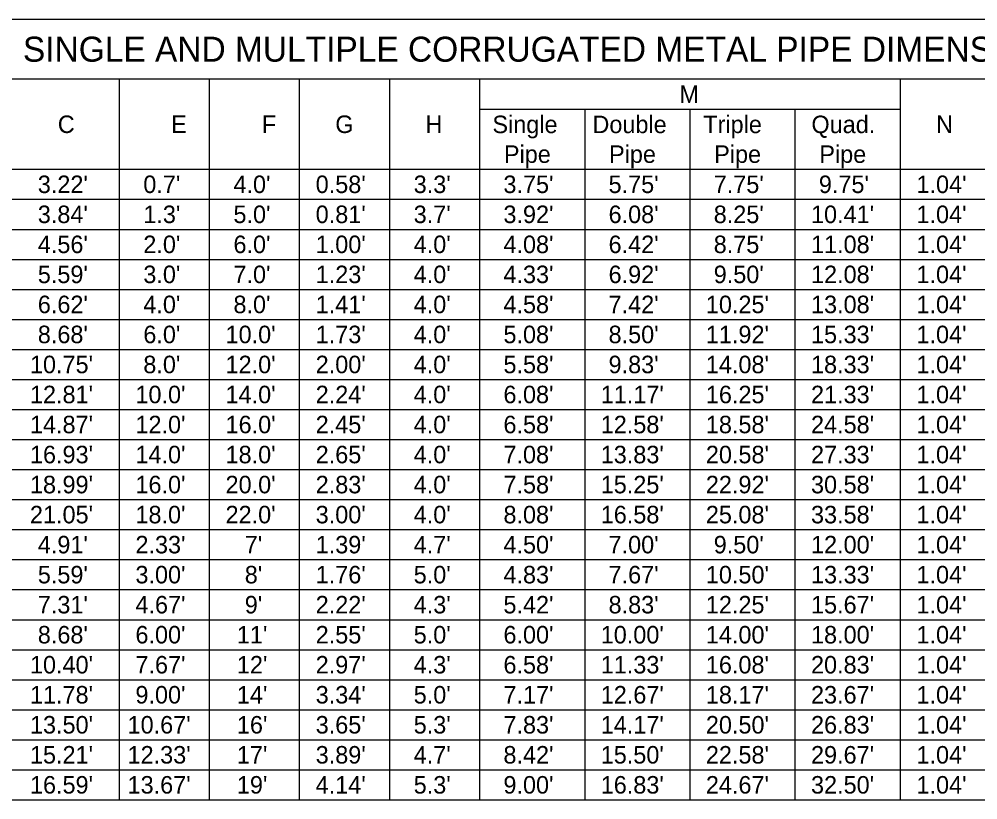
# Model space of a CAD drawing. Extents: x 2 to 14.4, y 0 to 6.5.
# Drawn here: x 4.481 to 8.31, y 3.39 to 6.51 of the extents above; entities that cross this region are included whole.
import ezdxf

# ---------------------------------------------------------------- set-up
doc = ezdxf.new("R2010")
doc.units = 0
doc.layers.add('TextNotes', color=7, linetype='Continuous')
doc.layers.add('TextTables', color=7, linetype='Continuous')

msp = doc.modelspace()

# ---------------------------------------------------------------- linework, layer by layer
at = {"layer": 'TextTables'}
msp.add_line((2, 6.51), (13.4, 6.51), dxfattribs=at)
for points in [[(13.4, 6.27), (11.72, 6.27), (10.04, 6.27), (8.36, 6.27), (8, 6.27), (6.32, 6.27), (5.96, 6.27), (5.6, 6.27), (5.24, 6.27), (4.88, 6.27), (4.46, 6.27), (3.98, 6.27), (3.56, 6.27), (3.14, 6.27), (2.84, 6.27), (2.54, 6.27), (2.24, 6.27), (2, 6.27)], [(4.88, 6.27), (4.88, 5.91), (4.88, 5.79), (4.88, 5.67), (4.88, 5.55), (4.88, 5.43), (4.88, 5.31), (4.88, 5.19), (4.88, 5.07), (4.88, 4.95), (4.88, 4.83), (4.88, 4.71), (4.88, 4.59), (4.88, 4.47), (4.88, 4.35), (4.88, 4.23), (4.88, 4.11), (4.88, 3.99), (4.88, 3.87), (4.88, 3.75), (4.88, 3.63), (4.88, 3.51), (4.88, 3.39)], [(5.24, 6.27), (5.24, 5.91), (5.24, 5.79), (5.24, 5.67), (5.24, 5.55), (5.24, 5.43), (5.24, 5.31), (5.24, 5.19), (5.24, 5.07), (5.24, 4.95), (5.24, 4.83), (5.24, 4.71), (5.24, 4.59), (5.24, 4.47), (5.24, 4.35), (5.24, 4.23), (5.24, 4.11), (5.24, 3.99), (5.24, 3.87), (5.24, 3.75), (5.24, 3.63), (5.24, 3.51), (5.24, 3.39)], [(5.6, 6.27), (5.6, 5.91), (5.6, 5.79), (5.6, 5.67), (5.6, 5.55), (5.6, 5.43), (5.6, 5.31), (5.6, 5.19), (5.6, 5.07), (5.6, 4.95), (5.6, 4.83), (5.6, 4.71), (5.6, 4.59), (5.6, 4.47), (5.6, 4.35), (5.6, 4.23), (5.6, 4.11), (5.6, 3.99), (5.6, 3.87), (5.6, 3.75), (5.6, 3.63), (5.6, 3.51), (5.6, 3.39)], [(5.96, 6.27), (5.96, 5.91), (5.96, 5.79), (5.96, 5.67), (5.96, 5.55), (5.96, 5.43), (5.96, 5.31), (5.96, 5.19), (5.96, 5.07), (5.96, 4.95), (5.96, 4.83), (5.96, 4.71), (5.96, 4.59), (5.96, 4.47), (5.96, 4.35), (5.96, 4.23), (5.96, 4.11), (5.96, 3.99), (5.96, 3.87), (5.96, 3.75), (5.96, 3.63), (5.96, 3.51), (5.96, 3.39)], [(6.32, 6.27), (6.32, 6.15), (6.32, 5.91), (6.32, 5.79), (6.32, 5.67), (6.32, 5.55), (6.32, 5.43), (6.32, 5.31), (6.32, 5.19), (6.32, 5.07), (6.32, 4.95), (6.32, 4.83), (6.32, 4.71), (6.32, 4.59), (6.32, 4.47), (6.32, 4.35), (6.32, 4.23), (6.32, 4.11), (6.32, 3.99), (6.32, 3.87), (6.32, 3.75), (6.32, 3.63), (6.32, 3.51), (6.32, 3.39)], [(8, 6.27), (8, 6.15), (8, 5.91), (8, 5.79), (8, 5.67), (8, 5.55), (8, 5.43), (8, 5.31), (8, 5.19), (8, 5.07), (8, 4.95), (8, 4.83), (8, 4.71), (8, 4.59), (8, 4.47), (8, 4.35), (8, 4.23), (8, 4.11), (8, 3.99), (8, 3.87), (8, 3.75), (8, 3.63), (8, 3.51), (8, 3.39)], [(6.32, 6.15), (6.74, 6.15), (7.16, 6.15), (7.58, 6.15), (8, 6.15)], [(6.74, 6.15), (6.74, 5.91), (6.74, 5.79), (6.74, 5.67), (6.74, 5.55), (6.74, 5.43), (6.74, 5.31), (6.74, 5.19), (6.74, 5.07), (6.74, 4.95), (6.74, 4.83), (6.74, 4.71), (6.74, 4.59), (6.74, 4.47), (6.74, 4.35), (6.74, 4.23), (6.74, 4.11), (6.74, 3.99), (6.74, 3.87), (6.74, 3.75), (6.74, 3.63), (6.74, 3.51), (6.74, 3.39)], [(7.16, 6.15), (7.16, 5.91), (7.16, 5.79), (7.16, 5.67), (7.16, 5.55), (7.16, 5.43), (7.16, 5.31), (7.16, 5.19), (7.16, 5.07), (7.16, 4.95), (7.16, 4.83), (7.16, 4.71), (7.16, 4.59), (7.16, 4.47), (7.16, 4.35), (7.16, 4.23), (7.16, 4.11), (7.16, 3.99), (7.16, 3.87), (7.16, 3.75), (7.16, 3.63), (7.16, 3.51), (7.16, 3.39)], [(7.58, 6.15), (7.58, 5.91), (7.58, 5.79), (7.58, 5.67), (7.58, 5.55), (7.58, 5.43), (7.58, 5.31), (7.58, 5.19), (7.58, 5.07), (7.58, 4.95), (7.58, 4.83), (7.58, 4.71), (7.58, 4.59), (7.58, 4.47), (7.58, 4.35), (7.58, 4.23), (7.58, 4.11), (7.58, 3.99), (7.58, 3.87), (7.58, 3.75), (7.58, 3.63), (7.58, 3.51), (7.58, 3.39)], [(2, 5.91), (2.24, 5.91), (2.54, 5.91), (2.84, 5.91), (3.14, 5.91), (3.56, 5.91), (3.98, 5.91), (4.46, 5.91), (4.88, 5.91), (5.24, 5.91), (5.6, 5.91), (5.96, 5.91), (6.32, 5.91), (6.74, 5.91), (7.16, 5.91), (7.58, 5.91), (8, 5.91), (8.36, 5.91)], [(2.24, 5.79), (2.54, 5.79), (2.84, 5.79), (3.14, 5.79), (3.56, 5.79), (3.98, 5.79), (4.46, 5.79), (4.88, 5.79), (5.24, 5.79), (5.6, 5.79), (5.96, 5.79), (6.32, 5.79), (6.74, 5.79), (7.16, 5.79), (7.58, 5.79), (8, 5.79), (8.36, 5.79)], [(2.24, 5.67), (2.54, 5.67), (2.84, 5.67), (3.14, 5.67), (3.56, 5.67), (3.98, 5.67), (4.46, 5.67), (4.88, 5.67), (5.24, 5.67), (5.6, 5.67), (5.96, 5.67), (6.32, 5.67), (6.74, 5.67), (7.16, 5.67), (7.58, 5.67), (8, 5.67), (8.36, 5.67)], [(2.24, 5.55), (2.54, 5.55), (2.84, 5.55), (3.14, 5.55), (3.56, 5.55), (3.98, 5.55), (4.46, 5.55), (4.88, 5.55), (5.24, 5.55), (5.6, 5.55), (5.96, 5.55), (6.32, 5.55), (6.74, 5.55), (7.16, 5.55), (7.58, 5.55), (8, 5.55), (8.36, 5.55)], [(2.24, 5.43), (2.54, 5.43), (2.84, 5.43), (3.14, 5.43), (3.56, 5.43), (3.98, 5.43), (4.46, 5.43), (4.88, 5.43), (5.24, 5.43), (5.6, 5.43), (5.96, 5.43), (6.32, 5.43), (6.74, 5.43), (7.16, 5.43), (7.58, 5.43), (8, 5.43), (8.36, 5.43)], [(2.24, 5.31), (2.54, 5.31), (2.84, 5.31), (3.14, 5.31), (3.56, 5.31), (3.98, 5.31), (4.46, 5.31), (4.88, 5.31), (5.24, 5.31), (5.6, 5.31), (5.96, 5.31), (6.32, 5.31), (6.74, 5.31), (7.16, 5.31), (7.58, 5.31), (8, 5.31), (8.36, 5.31)], [(2.24, 5.19), (2.54, 5.19), (2.84, 5.19), (3.14, 5.19), (3.56, 5.19), (3.98, 5.19), (4.46, 5.19), (4.88, 5.19), (5.24, 5.19), (5.6, 5.19), (5.96, 5.19), (6.32, 5.19), (6.74, 5.19), (7.16, 5.19), (7.58, 5.19), (8, 5.19), (8.36, 5.19)], [(2.24, 5.07), (2.54, 5.07), (2.84, 5.07), (3.14, 5.07), (3.56, 5.07), (3.98, 5.07), (4.46, 5.07), (4.88, 5.07), (5.24, 5.07), (5.6, 5.07), (5.96, 5.07), (6.32, 5.07), (6.74, 5.07), (7.16, 5.07), (7.58, 5.07), (8, 5.07), (8.36, 5.07)], [(2.24, 4.95), (2.54, 4.95), (2.84, 4.95), (3.14, 4.95), (3.56, 4.95), (3.98, 4.95), (4.46, 4.95), (4.88, 4.95), (5.24, 4.95), (5.6, 4.95), (5.96, 4.95), (6.32, 4.95), (6.74, 4.95), (7.16, 4.95), (7.58, 4.95), (8, 4.95), (8.36, 4.95)], [(2.24, 4.83), (2.54, 4.83), (2.84, 4.83), (3.14, 4.83), (3.56, 4.83), (3.98, 4.83), (4.46, 4.83), (4.88, 4.83), (5.24, 4.83), (5.6, 4.83), (5.96, 4.83), (6.32, 4.83), (6.74, 4.83), (7.16, 4.83), (7.58, 4.83), (8, 4.83), (8.36, 4.83)], [(2.24, 4.71), (2.54, 4.71), (2.84, 4.71), (3.14, 4.71), (3.56, 4.71), (3.98, 4.71), (4.46, 4.71), (4.88, 4.71), (5.24, 4.71), (5.6, 4.71), (5.96, 4.71), (6.32, 4.71), (6.74, 4.71), (7.16, 4.71), (7.58, 4.71), (8, 4.71), (8.36, 4.71)], [(2.24, 4.59), (2.54, 4.59), (2.84, 4.59), (3.14, 4.59), (3.56, 4.59), (3.98, 4.59), (4.46, 4.59), (4.88, 4.59), (5.24, 4.59), (5.6, 4.59), (5.96, 4.59), (6.32, 4.59), (6.74, 4.59), (7.16, 4.59), (7.58, 4.59), (8, 4.59), (8.36, 4.59)], [(2, 4.47), (2.24, 4.47), (2.54, 4.47), (2.84, 4.47), (3.14, 4.47), (3.56, 4.47), (3.98, 4.47), (4.46, 4.47), (4.88, 4.47), (5.24, 4.47), (5.6, 4.47), (5.96, 4.47), (6.32, 4.47), (6.74, 4.47), (7.16, 4.47), (7.58, 4.47), (8, 4.47), (8.36, 4.47)], [(2.24, 4.47), (2.54, 4.47), (2.84, 4.47), (3.14, 4.47), (3.56, 4.47), (3.98, 4.47), (4.46, 4.47), (4.88, 4.47), (5.24, 4.47), (5.6, 4.47), (5.96, 4.47), (6.32, 4.47), (6.74, 4.47), (7.16, 4.47), (7.58, 4.47), (8, 4.47), (8.36, 4.47)], [(2.24, 4.35), (2.54, 4.35), (2.84, 4.35), (3.14, 4.35), (3.56, 4.35), (3.98, 4.35), (4.46, 4.35), (4.88, 4.35), (5.24, 4.35), (5.6, 4.35), (5.96, 4.35), (6.32, 4.35), (6.74, 4.35), (7.16, 4.35), (7.58, 4.35), (8, 4.35), (8.36, 4.35)], [(2.24, 4.23), (2.54, 4.23), (2.84, 4.23), (3.14, 4.23), (3.56, 4.23), (3.98, 4.23), (4.46, 4.23), (4.88, 4.23), (5.24, 4.23), (5.6, 4.23), (5.96, 4.23), (6.32, 4.23), (6.74, 4.23), (7.16, 4.23), (7.58, 4.23), (8, 4.23), (8.36, 4.23)], [(2.24, 4.11), (2.54, 4.11), (2.84, 4.11), (3.14, 4.11), (3.56, 4.11), (3.98, 4.11), (4.46, 4.11), (4.88, 4.11), (5.24, 4.11), (5.6, 4.11), (5.96, 4.11), (6.32, 4.11), (6.74, 4.11), (7.16, 4.11), (7.58, 4.11), (8, 4.11), (8.36, 4.11)], [(2.24, 3.99), (2.54, 3.99), (2.84, 3.99), (3.14, 3.99), (3.56, 3.99), (3.98, 3.99), (4.46, 3.99), (4.88, 3.99), (5.24, 3.99), (5.6, 3.99), (5.96, 3.99), (6.32, 3.99), (6.74, 3.99), (7.16, 3.99), (7.58, 3.99), (8, 3.99), (8.36, 3.99)], [(2.24, 3.87), (2.54, 3.87), (2.84, 3.87), (3.14, 3.87), (3.56, 3.87), (3.98, 3.87), (4.46, 3.87), (4.88, 3.87), (5.24, 3.87), (5.6, 3.87), (5.96, 3.87), (6.32, 3.87), (6.74, 3.87), (7.16, 3.87), (7.58, 3.87), (8, 3.87), (8.36, 3.87)], [(2.24, 3.75), (2.54, 3.75), (2.84, 3.75), (3.14, 3.75), (3.56, 3.75), (3.98, 3.75), (4.46, 3.75), (4.88, 3.75), (5.24, 3.75), (5.6, 3.75), (5.96, 3.75), (6.32, 3.75), (6.74, 3.75), (7.16, 3.75), (7.58, 3.75), (8, 3.75), (8.36, 3.75)], [(2.24, 3.63), (2.54, 3.63), (2.84, 3.63), (3.14, 3.63), (3.56, 3.63), (3.98, 3.63), (4.46, 3.63), (4.88, 3.63), (5.24, 3.63), (5.6, 3.63), (5.96, 3.63), (6.32, 3.63), (6.74, 3.63), (7.16, 3.63), (7.58, 3.63), (8, 3.63), (8.36, 3.63)], [(2.24, 3.51), (2.54, 3.51), (2.84, 3.51), (3.14, 3.51), (3.56, 3.51), (3.98, 3.51), (4.46, 3.51), (4.88, 3.51), (5.24, 3.51), (5.6, 3.51), (5.96, 3.51), (6.32, 3.51), (6.74, 3.51), (7.16, 3.51), (7.58, 3.51), (8, 3.51), (8.36, 3.51)], [(2, 3.39), (2.24, 3.39), (2.54, 3.39), (2.84, 3.39), (3.14, 3.39), (3.56, 3.39), (3.98, 3.39), (4.46, 3.39), (4.88, 3.39), (5.24, 3.39), (5.6, 3.39), (5.96, 3.39), (6.32, 3.39), (6.74, 3.39), (7.16, 3.39), (7.58, 3.39), (8, 3.39), (8.36, 3.39)]]:
    msp.add_lwpolyline(points, dxfattribs=at)

# ---------------------------------------------------------------- texts
at = {"layer": 'TextNotes'}
for s, height, p in [('SINGLE AND MULTIPLE CORRUGATED METAL PIPE DIMENSIONS AND QUANTITIES', 0.1, (4.4959, 6.34)), ('M', 0.07, (7.1183, 6.175)), ('Single', 0.07, (6.3714, 6.0545)), ('Double', 0.07, (6.7709, 6.0545)), ('Triple', 0.07, (7.2137, 6.0545)), ('Quad.', 0.07, (7.6457, 6.0545)), ('C', 0.07, (4.6352, 6.055)), ('E', 0.07, (5.0882, 6.055)), ('F', 0.07, (5.4503, 6.055)), ('G', 0.07, (5.7438, 6.055)), ('H', 0.07, (6.1037, 6.055)), ('N', 0.07, (8.1438, 6.055)), ('Pipe', 0.07, (6.4173, 5.9355)), ('Pipe', 0.07, (6.8373, 5.9355)), ('Pipe', 0.07, (7.2573, 5.9355)), ('Pipe', 0.07, (7.6773, 5.9355))]:
    msp.add_text(s, height=height, dxfattribs=at).set_placement(p)
for s, p in [("3.22'", (4.5554, 5.815)), ("0.7'", (4.9769, 5.815)), ("4.0'", (5.3369, 5.815)), ("0.58'", (5.6654, 5.815)), ("3.3'", (6.0569, 5.815)), ("3.75'", (6.4154, 5.815)), ("5.75'", (6.8354, 5.815)), ("7.75'", (7.2554, 5.815)), ("9.75'", (7.6754, 5.815)), ("1.04'", (8.0654, 5.815)), ("3.84'", (4.5554, 5.695)), ("1.3'", (4.9769, 5.695)), ("5.0'", (5.3369, 5.695)), ("0.81'", (5.6654, 5.695)), ("3.7'", (6.0569, 5.695)), ("3.92'", (6.4154, 5.695)), ("6.08'", (6.8354, 5.695)), ("8.25'", (7.2554, 5.695)), ("10.41'", (7.644, 5.695)), ("1.04'", (8.0654, 5.695)), ("4.56'", (4.5554, 5.575)), ("2.0'", (4.9769, 5.575)), ("6.0'", (5.3369, 5.575)), ("1.00'", (5.6654, 5.575)), ("4.0'", (6.0569, 5.575)), ("4.08'", (6.4154, 5.575)), ("6.42'", (6.8354, 5.575)), ("8.75'", (7.2554, 5.575)), ("11.08'", (7.644, 5.575)), ("1.04'", (8.0654, 5.575)), ("5.59'", (4.5554, 5.455)), ("3.0'", (4.9769, 5.455)), ("7.0'", (5.3369, 5.455)), ("1.23'", (5.6654, 5.455)), ("4.0'", (6.0569, 5.455)), ("4.33'", (6.4154, 5.455)), ("6.92'", (6.8354, 5.455)), ("9.50'", (7.2554, 5.455)), ("12.08'", (7.644, 5.455)), ("1.04'", (8.0654, 5.455)), ("6.62'", (4.5554, 5.335)), ("4.0'", (4.9769, 5.335)), ("8.0'", (5.3369, 5.335)), ("1.41'", (5.6654, 5.335)), ("4.0'", (6.0569, 5.335)), ("4.58'", (6.4154, 5.335)), ("7.42'", (6.8354, 5.335)), ("10.25'", (7.224, 5.335)), ("13.08'", (7.644, 5.335)), ("1.04'", (8.0654, 5.335)), ("8.68'", (4.5554, 5.215)), ("6.0'", (4.9769, 5.215)), ("10.0'", (5.3054, 5.215)), ("1.73'", (5.6654, 5.215)), ("4.0'", (6.0569, 5.215)), ("5.08'", (6.4154, 5.215)), ("8.50'", (6.8354, 5.215)), ("11.92'", (7.224, 5.215)), ("15.33'", (7.644, 5.215)), ("1.04'", (8.0654, 5.215)), ("10.75'", (4.524, 5.095)), ("8.0'", (4.9769, 5.095)), ("12.0'", (5.3054, 5.095)), ("2.00'", (5.6654, 5.095)), ("4.0'", (6.0569, 5.095)), ("5.58'", (6.4154, 5.095)), ("9.83'", (6.8354, 5.095)), ("14.08'", (7.224, 5.095)), ("18.33'", (7.644, 5.095)), ("1.04'", (8.0654, 5.095)), ("12.81'", (4.524, 4.975)), ("10.0'", (4.9454, 4.975)), ("14.0'", (5.3054, 4.975)), ("2.24'", (5.6654, 4.975)), ("4.0'", (6.0569, 4.975)), ("6.08'", (6.4154, 4.975)), ("11.17'", (6.804, 4.975)), ("16.25'", (7.224, 4.975)), ("21.33'", (7.644, 4.975)), ("1.04'", (8.0654, 4.975)), ("14.87'", (4.524, 4.855)), ("12.0'", (4.9454, 4.855)), ("16.0'", (5.3054, 4.855)), ("2.45'", (5.6654, 4.855)), ("4.0'", (6.0569, 4.855)), ("6.58'", (6.4154, 4.855)), ("12.58'", (6.804, 4.855)), ("18.58'", (7.224, 4.855)), ("24.58'", (7.644, 4.855)), ("1.04'", (8.0654, 4.855)), ("16.93'", (4.524, 4.735)), ("14.0'", (4.9454, 4.735)), ("18.0'", (5.3054, 4.735)), ("2.65'", (5.6654, 4.735)), ("4.0'", (6.0569, 4.735)), ("7.08'", (6.4154, 4.735)), ("13.83'", (6.804, 4.735)), ("20.58'", (7.224, 4.735)), ("27.33'", (7.644, 4.735)), ("1.04'", (8.0654, 4.735)), ("18.99'", (4.524, 4.615)), ("16.0'", (4.9454, 4.615)), ("20.0'", (5.3054, 4.615)), ("2.83'", (5.6654, 4.615)), ("4.0'", (6.0569, 4.615)), ("7.58'", (6.4154, 4.615)), ("15.25'", (6.804, 4.615)), ("22.92'", (7.224, 4.615)), ("30.58'", (7.644, 4.615)), ("1.04'", (8.0654, 4.615)), ("21.05'", (4.524, 4.495)), ("18.0'", (4.9454, 4.495)), ("22.0'", (5.3054, 4.495)), ("3.00'", (5.6654, 4.495)), ("4.0'", (6.0569, 4.495)), ("8.08'", (6.4154, 4.495)), ("16.58'", (6.804, 4.495)), ("25.08'", (7.224, 4.495)), ("33.58'", (7.644, 4.495)), ("1.04'", (8.0654, 4.495)), ("4.91'", (4.5554, 4.375)), ("2.33'", (4.9454, 4.375)), ("7'", (5.3821, 4.375)), ("1.39'", (5.6654, 4.375)), ("4.7'", (6.0569, 4.375)), ("4.50'", (6.4154, 4.375)), ("7.00'", (6.8354, 4.375)), ("9.50'", (7.2554, 4.375)), ("12.00'", (7.644, 4.375)), ("1.04'", (8.0654, 4.375)), ("5.59'", (4.5554, 4.255)), ("3.00'", (4.9454, 4.255)), ("8'", (5.3821, 4.255)), ("1.76'", (5.6654, 4.255)), ("5.0'", (6.0569, 4.255)), ("4.83'", (6.4154, 4.255)), ("7.67'", (6.8354, 4.255)), ("10.50'", (7.224, 4.255)), ("13.33'", (7.644, 4.255)), ("1.04'", (8.0654, 4.255)), ("7.31'", (4.5554, 4.135)), ("4.67'", (4.9454, 4.135)), ("9'", (5.3821, 4.135)), ("2.22'", (5.6654, 4.135)), ("4.3'", (6.0569, 4.135)), ("5.42'", (6.4154, 4.135)), ("8.83'", (6.8354, 4.135)), ("12.25'", (7.224, 4.135)), ("15.67'", (7.644, 4.135)), ("1.04'", (8.0654, 4.135)), ("8.68'", (4.5554, 4.015)), ("6.00'", (4.9454, 4.015)), ("11'", (5.3506, 4.015)), ("2.55'", (5.6654, 4.015)), ("5.0'", (6.0569, 4.015)), ("6.00'", (6.4154, 4.015)), ("10.00'", (6.804, 4.015)), ("14.00'", (7.224, 4.015)), ("18.00'", (7.644, 4.015)), ("1.04'", (8.0654, 4.015)), ("10.40'", (4.524, 3.895)), ("7.67'", (4.9454, 3.895)), ("12'", (5.3506, 3.895)), ("2.97'", (5.6654, 3.895)), ("4.3'", (6.0569, 3.895)), ("6.58'", (6.4154, 3.895)), ("11.33'", (6.804, 3.895)), ("16.08'", (7.224, 3.895)), ("20.83'", (7.644, 3.895)), ("1.04'", (8.0654, 3.895)), ("11.78'", (4.524, 3.775)), ("9.00'", (4.9454, 3.775)), ("14'", (5.3506, 3.775)), ("3.34'", (5.6654, 3.775)), ("5.0'", (6.0569, 3.775)), ("7.17'", (6.4154, 3.775)), ("12.67'", (6.804, 3.775)), ("18.17'", (7.224, 3.775)), ("23.67'", (7.644, 3.775)), ("1.04'", (8.0654, 3.775)), ("13.50'", (4.524, 3.655)), ("10.67'", (4.914, 3.655)), ("16'", (5.3506, 3.655)), ("3.65'", (5.6654, 3.655)), ("5.3'", (6.0569, 3.655)), ("7.83'", (6.4154, 3.655)), ("14.17'", (6.804, 3.655)), ("20.50'", (7.224, 3.655)), ("26.83'", (7.644, 3.655)), ("1.04'", (8.0654, 3.655)), ("15.21'", (4.524, 3.535)), ("12.33'", (4.914, 3.535)), ("17'", (5.3506, 3.535)), ("3.89'", (5.6654, 3.535)), ("4.7'", (6.0569, 3.535)), ("8.42'", (6.4154, 3.535)), ("15.50'", (6.804, 3.535)), ("22.58'", (7.224, 3.535)), ("29.67'", (7.644, 3.535)), ("1.04'", (8.0654, 3.535)), ("16.59'", (4.524, 3.415)), ("13.67'", (4.914, 3.415)), ("19'", (5.3506, 3.415)), ("4.14'", (5.6654, 3.415)), ("5.3'", (6.0569, 3.415)), ("9.00'", (6.4154, 3.415)), ("16.83'", (6.804, 3.415)), ("24.67'", (7.224, 3.415)), ("32.50'", (7.644, 3.415)), ("1.04'", (8.0654, 3.415))]:
    msp.add_text(s, height=0.07, rotation=0, dxfattribs=at).set_placement(p)

doc.saveas('drawing.dxf')
